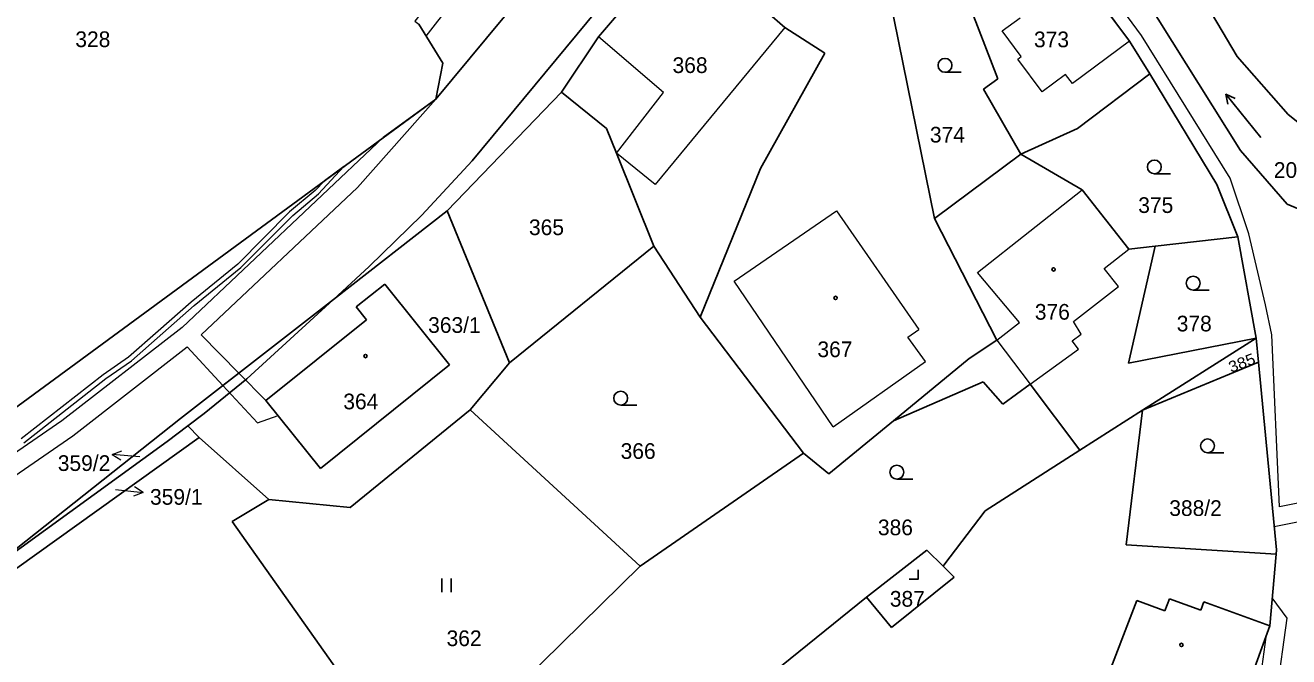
# Model space of a CAD drawing. Extents: x -727701 to -724405, y -960481 to -957284.
# Drawn here: x -726949 to -726812.2, y -958276.3 to -958207.9 of the extents above; entities that cross this region are included whole.
import ezdxf
from ezdxf.enums import TextEntityAlignment as Align

# ---------------------------------------------------------------- set-up
doc = ezdxf.new("R2010")
doc.units = 0
doc.header["$LTSCALE"] = 0.68
for name, color, linetype, lineweight in [('1', 7, 'Continuous', 25), ('13', 7, 'Continuous', 13), ('3', 7, 'Continuous', 25), ('4', 7, 'Continuous', 13), ('5', 7, 'Continuous', 25), ('7', 7, 'Continuous', 13)]:
    doc.layers.add(name, color=color, linetype=linetype, lineweight=lineweight)
doc.layers.add('2', color=7, linetype='Continuous')

msp = doc.modelspace()

# ---------------------------------------------------------------- linework, layer by layer
at = {"layer": '1'}
for p, q in [((-726900.64, -958222.58), (-726861.79, -958175.64)), ((-726829.44, -958209.62), (-726838.98, -958196.8)), ((-726833.04, -958196.58), (-726817.41, -958221.47)), ((-726904.57, -958215.89), (-726889.27, -958197.45)), ((-726843.71, -958213.69), (-726850.03, -958197.22)), ((-726825.9, -958197.5), (-726817.77, -958211.3)), ((-726886.95, -958209.14), (-726877.83, -958198.47)), ((-726866.77, -958208.14), (-726877.83, -958198.47)), ((-726850.58, -958228.82), (-726855.64, -958203.88)), ((-726903.79, -958212.02), (-726906.42, -958207.78)), ((-726890.94, -958215.16), (-726886.95, -958209.14)), ((-726862.42, -958210.91), (-726866.77, -958208.14)), ((-726827.26, -958213.17), (-726829.44, -958209.62)), ((-726869.41, -958223.41), (-726862.42, -958210.91)), ((-726817.77, -958211.3), (-726812.27, -958217.58)), ((-726904.57, -958215.89), (-726903.79, -958212.02)), ((-726835.09, -958219.08), (-726827.26, -958213.17)), ((-726820, -958225.15), (-726827.26, -958213.17)), ((-726904.57, -958215.89), (-726959.25, -958256.05)), ((-726903.32, -958228.01), (-726890.94, -958215.16)), ((-726890.94, -958215.16), (-726886.07, -958219.07)), ((-726812.27, -958217.58), (-726804.87, -958223.44)), ((-726886.07, -958219.07), (-726885, -958221.74)), ((-726841.2, -958221.87), (-726835.09, -958219.08)), ((-726817.41, -958221.47), (-726812.38, -958227.27)), ((-726906.06, -958228.47), (-726900.64, -958222.58)), ((-726885, -958221.74), (-726880.94, -958231.83)), ((-726850.58, -958228.82), (-726841.2, -958221.87)), ((-726834.58, -958225.74), (-726841.2, -958221.87)), ((-726875.95, -958239.53), (-726869.41, -958223.41)), ((-726817.7, -958230.82), (-726820, -958225.15)), ((-726829.53, -958232.14), (-726834.58, -958225.74)), ((-726812.38, -958227.27), (-726808.33, -958228.97)), ((-726911.77, -958234.04), (-726906.06, -958228.47)), ((-726843.8, -958242), (-726850.58, -958228.82)), ((-726826.66, -958231.83), (-726817.7, -958230.82)), ((-726815.74, -958241.81), (-726817.7, -958230.82)), ((-726896.57, -958244.47), (-726880.94, -958231.83)), ((-726880.94, -958231.83), (-726875.95, -958239.53)), ((-726826.66, -958231.83), (-726829.56, -958244.51)), ((-726829.53, -958232.14), (-726826.66, -958231.83)), ((-726915.65, -958237.61), (-726911.77, -958234.04)), ((-726913.18, -958238.41), (-726910.07, -958235.95)), ((-726910.07, -958235.95), (-726903.07, -958244.69)), ((-726932.2, -958250.5), (-726915.65, -958237.61)), ((-726915.65, -958237.61), (-726925.01, -958246.22)), ((-726912.07, -958239.81), (-726913.18, -958238.41)), ((-726922.98, -958248.54), (-726912.07, -958239.81)), ((-726864.74, -958254.25), (-726875.95, -958239.53)), ((-726846.8, -958244), (-726843.8, -958242)), ((-726829.56, -958244.51), (-726815.74, -958241.81)), ((-726828.04, -958249.61), (-726815.74, -958241.81)), ((-726815.49, -958244.38), (-726815.74, -958241.81)), ((-726903.07, -958244.69), (-726917.05, -958255.92)), ((-726900.84, -958249.57), (-726896.57, -958244.47)), ((-726855.02, -958250.76), (-726846.8, -958244)), ((-726828.04, -958249.61), (-726815.49, -958244.38)), ((-726813.54, -958264.72), (-726815.49, -958244.38)), ((-726925.01, -958246.22), (-726929.65, -958249.97)), ((-726855.02, -958250.76), (-726845.29, -958246.54)), ((-726845.29, -958246.54), (-726843.17, -958248.93)), ((-726843.17, -958248.93), (-726840.2, -958246.79)), ((-726840.2, -958246.79), (-726834.81, -958253.94)), ((-726917.05, -958255.92), (-726922.98, -958248.54)), ((-726929.65, -958249.97), (-726931.42, -958251.3)), ((-726913.83, -958260.13), (-726900.84, -958249.57)), ((-726882.45, -958266.5), (-726900.84, -958249.57)), ((-726834.81, -958253.94), (-726828.04, -958249.61)), ((-726828.04, -958249.61), (-726829.8, -958264.17)), ((-726953.33, -958267.25), (-726932.2, -958250.5)), ((-726931.42, -958251.3), (-726933.65, -958252.98)), ((-726931.42, -958251.3), (-726930.2, -958252.54)), ((-726862, -958256.5), (-726855.02, -958250.76)), ((-726933.65, -958252.98), (-726953.33, -958267.25)), ((-726952.12, -958268.28), (-726930.2, -958252.54)), ((-726930.2, -958252.54), (-726922.63, -958259.26)), ((-726882.45, -958266.5), (-726864.74, -958254.25)), ((-726864.74, -958254.25), (-726862, -958256.5)), ((-726845.07, -958260.5), (-726834.81, -958253.94)), ((-726926.62, -958261.65), (-726922.63, -958259.26)), ((-726922.63, -958259.26), (-726913.83, -958260.13)), ((-726845.07, -958260.5), (-726849.55, -958266.4)), ((-726905.86, -958290.97), (-726926.62, -958261.65)), ((-726851.41, -958264.75), (-726857.92, -958269.86)), ((-726851.41, -958264.75), (-726849.64, -958266.5)), ((-726829.8, -958264.17), (-726813.58, -958265.2)), ((-726814.24, -958272.97), (-726813.58, -958265.2)), ((-726813.58, -958265.2), (-726813.54, -958264.72)), ((-726895.18, -958279.02), (-726882.45, -958266.5)), ((-726849.55, -958266.4), (-726849.64, -958266.5)), ((-726849.64, -958266.5), (-726848.45, -958267.68)), ((-726848.45, -958267.68), (-726855.23, -958273.14)), ((-726879.98, -958287.63), (-726857.92, -958269.86)), ((-726857.92, -958269.86), (-726855.23, -958273.14)), ((-726833.27, -958282.26), (-726828.66, -958270.21)), ((-726828.66, -958270.21), (-726825.61, -958271.32)), ((-726825.61, -958271.32), (-726825.13, -958270.02)), ((-726825.13, -958270.02), (-726821.72, -958271.27)), ((-726821.72, -958271.27), (-726821.39, -958270.35)), ((-726821.39, -958270.35), (-726814.24, -958272.97)), ((-726818.93, -958285.76), (-726814.24, -958272.97))]:
    msp.add_line(p, q, dxfattribs=at)
for points in [[(-726843.71, -958213.69), (-726845.25, -958214.84), (-726841.2, -958221.87)], [(-726915.65, -958237.61), (-726903.32, -958228.01), (-726896.57, -958244.47)]]:
    msp.add_lwpolyline(points, dxfattribs=at)
at = {"layer": '13'}
for points in [[(-726889.41, -958188.3), (-726892.58, -958190.92), (-726900.07, -958198.86), (-726902.35, -958201.76), (-726906.85, -958207.46), (-726906.42, -958207.78), (-726905.6, -958209.1), (-726900.26, -958202.2), (-726899.04, -958200.75), (-726898.56, -958200.17), (-726891.21, -958192.38), (-726888.45, -958190.09), (-726886.78, -958189.59), (-726884.37, -958191.53), (-726883.09, -958189.99), (-726886.36, -958187.37)], [(-726910.26, -958220.07), (-726932.03, -958240.64), (-726945.05, -958250.77), (-726983.47, -958277.23), (-726977.29, -958285.71), (-726975.64, -958284.57), (-726980.64, -958277.71), (-726943.87, -958252.39), (-726931.49, -958242.75), (-726927.62, -958246.93), (-726925.89, -958245.59), (-726929.97, -958241.44), (-726913.05, -958225.46), (-726904.57, -958215.89)], [(-726927.62, -958246.93), (-726923.88, -958250.98), (-726921.65, -958250.19), (-726922.98, -958248.54), (-726925.89, -958245.59)], [(-726813.98, -958269.94), (-726814.24, -958272.97), (-726814.68, -958274.17), (-726815.32, -958278.95), (-726816.7, -958279.69), (-726818.93, -958285.76), (-726818.95, -958287.51), (-726819.58, -958289.65), (-726820.64, -958291.68), (-726820.56, -958302.76), (-726819.07, -958301.91), (-726818.8, -958292.08), (-726815.44, -958281.28), (-726813.48, -958280.23), (-726812.39, -958272.12)]]:
    msp.add_lwpolyline(points, close=True, dxfattribs=at)
for points in [[(-726838.98, -958196.8), (-726829.44, -958209.62), (-726827.26, -958213.17), (-726820, -958225.15), (-726817.7, -958230.82), (-726815.74, -958241.81), (-726815.49, -958244.38), (-726813.78, -958262.21), (-726800.4, -958259.53)], [(-726798.94, -958257.2), (-726813.2, -958260.06), (-726814.02, -958241.42), (-726814.72, -958238.17), (-726816.54, -958230.51), (-726818.53, -958224.46), (-726828.14, -958209.01), (-726831.19, -958204.87)], [(-726949.17, -958253.13), (-726940.29, -958246.17), (-726937.52, -958244.24), (-726930.74, -958238.27), (-726925.68, -958234.14), (-726925.54, -958234.01), (-726920.05, -958228.5), (-726917.27, -958226.17), (-726914.51, -958223.19), (-726916.63, -958224.75), (-726917.62, -958225.81), (-726920.39, -958228.13), (-726926.01, -958233.77), (-726931.06, -958237.89), (-726934.64, -958241.04), (-726937.83, -958243.84), (-726940.58, -958245.77), (-726949.46, -958252.72)]]:
    msp.add_lwpolyline(points, dxfattribs=at)
at = {"layer": '3'}
for p, q in [((-726849.423, -958212.99), (-726847.673, -958212.99)), ((-726819.012, -958215.38), (-726818.007, -958215.824)), ((-726826.753, -958224), (-726825.003, -958224)), ((-726822.553, -958236.59), (-726820.803, -958236.59)), ((-726884.543, -958249.05), (-726882.793, -958249.05)), ((-726820.993, -958254.22), (-726819.243, -958254.22)), ((-726854.643, -958257.07), (-726852.893, -958257.07)), ((-726903.911, -958269.33), (-726903.911, -958267.83)), ((-726902.91, -958269.33), (-726902.91, -958267.83))]:
    msp.add_line(p, q, dxfattribs=at)
for points in [[(-726815.236, -958220.043), (-726819.012, -958215.38), (-726818.787, -958216.455)], [(-726853.321, -958267.89), (-726852.32, -958267.89), (-726852.32, -958266.89)]]:
    msp.add_lwpolyline(points, dxfattribs=at)
for centre in [(-726849.4229, -958212.2398), (-726826.7529, -958223.2498), (-726822.5529, -958235.8398), (-726884.5429, -958248.2998), (-726820.9929, -958253.4698), (-726854.6429, -958256.3198)]:
    msp.add_circle(centre, 0.75, dxfattribs=at)
at = {"layer": '4'}
for p, q in [((-726843.22, -958208.52), (-726841.29, -958207.08)), ((-726879.9, -958215.17), (-726886.95, -958209.14)), ((-726866.77, -958208.14), (-726880.8, -958225.15)), ((-726841.17, -958211.28), (-726843.22, -958208.52)), ((-726829.44, -958209.62), (-726835.63, -958214.22)), ((-726841.55, -958211.56), (-726841.17, -958211.28)), ((-726838.91, -958215.1), (-726841.55, -958211.56)), ((-726836.37, -958213.22), (-726838.91, -958215.1)), ((-726835.63, -958214.22), (-726836.37, -958213.22)), ((-726885, -958221.74), (-726879.9, -958215.17)), ((-726880.8, -958225.15), (-726885, -958221.74)), ((-726845.91, -958234.68), (-726834.58, -958225.74)), ((-726872.25, -958235.64), (-726861.16, -958227.99)), ((-726861.16, -958227.99), (-726852.25, -958240.86)), ((-726832.19, -958234.24), (-726829.53, -958232.14)), ((-726841.34, -958240.1), (-726845.91, -958234.68)), ((-726830.65, -958236.19), (-726832.19, -958234.24)), ((-726861.53, -958251.39), (-726872.25, -958235.64)), ((-726835.5, -958240), (-726830.65, -958236.19)), ((-726843.8, -958242), (-726841.34, -958240.1)), ((-726834.68, -958241.37), (-726835.5, -958240)), ((-726853.44, -958241.69), (-726852.25, -958240.86)), ((-726851.53, -958244.34), (-726853.44, -958241.69)), ((-726843.8, -958242), (-726840.2, -958246.79)), ((-726835.64, -958242.07), (-726834.68, -958241.37)), ((-726834.97, -958242.99), (-726835.64, -958242.07)), ((-726840.2, -958246.79), (-726834.97, -958242.99)), ((-726861.53, -958251.39), (-726851.53, -958244.34))]:
    msp.add_line(p, q, dxfattribs=at)
at = {"layer": '5'}
for centre in [(-726837.6668, -958234.3492), (-726861.2768, -958237.4392), (-726912.1768, -958243.7392), (-726823.8268, -958275.0292)]:
    msp.add_circle(centre, 0.175, dxfattribs=at)
at = {"layer": '7'}
for p, q in [((-726939.61, -958254.398), (-726938.656, -958254.985)), ((-726936.255, -958258.504), (-726937.199, -958257.901))]:
    msp.add_line(p, q, dxfattribs=at)
for points in [[(-726936.62, -958254.66), (-726939.61, -958254.398), (-726938.568, -958253.987)], [(-726939.24, -958258.19), (-726936.255, -958258.504), (-726937.304, -958258.897)]]:
    msp.add_lwpolyline(points, dxfattribs=at)

# ---------------------------------------------------------------- texts
at = {"layer": '2'}
for s, p in [('328', (-726943.6, -958210.265)), ('373', (-726839.79, -958210.285)), ('368', (-726878.93, -958213.075)), ('374', (-726851.06, -958220.605)), ('201', (-726813.82, -958224.435)), ('375', (-726828.5, -958228.235)), ('376', (-726839.7, -958239.795)), ('378', (-726824.33, -958241.065)), ('367', (-726863.24, -958243.855)), ('364', (-726914.58, -958249.505)), ('366', (-726884.55, -958254.875)), ('359/1', (-726935.51, -958259.842)), ('388/2', (-726825.14, -958261.055)), ('386', (-726856.69, -958263.145)), ('387', (-726855.4, -958270.885)), ('362', (-726903.4, -958275.155))]:
    msp.add_text(s, height=1.7, dxfattribs=at).set_placement(p)
for s, p in [('365', (-726892.579, -958230.635)), ('363/1', (-726902.55, -958241.225))]:
    msp.add_text(s, height=1.7, dxfattribs=at).set_placement(p, align=Align.CENTER)
at = {"layer": '2', "width": 1.1}
msp.add_text('385', height=1.2, rotation=21, dxfattribs=at).set_placement((-726818.442, -958245.56))
at = {"layer": '2'}
msp.add_text('359/2', height=1.7, dxfattribs=at).set_placement((-726939.81, -958256.182), align=Align.RIGHT)

doc.saveas('drawing.dxf')
